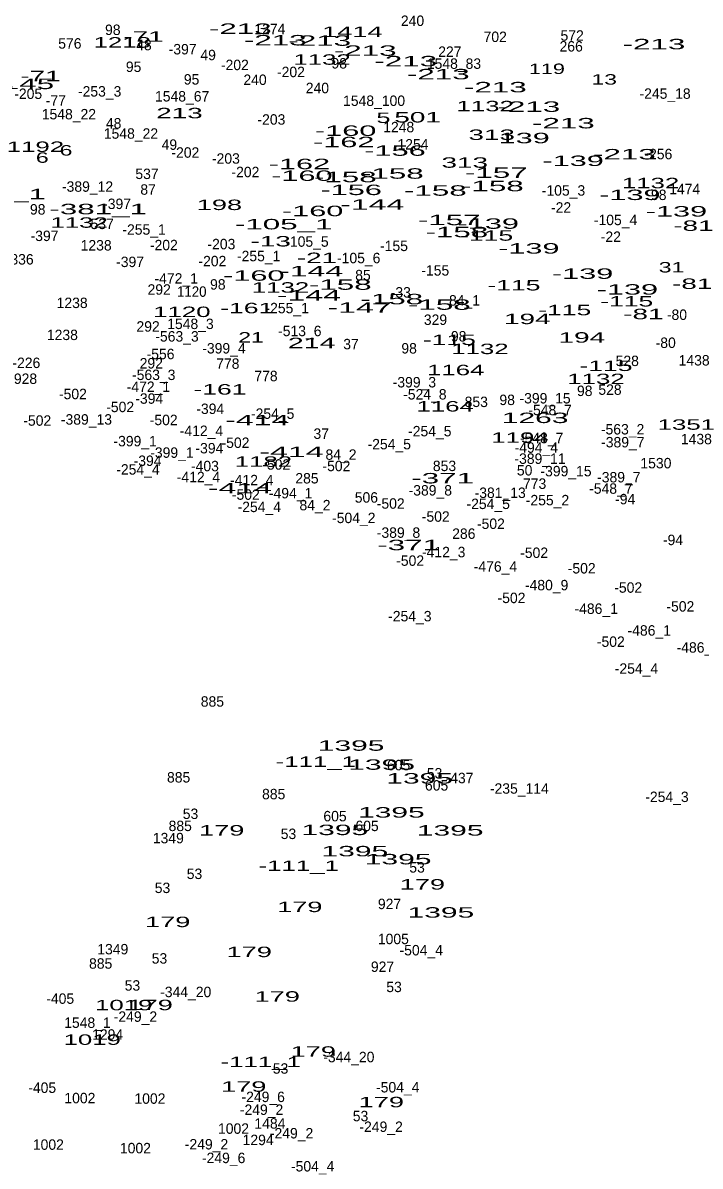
# Model space of a CAD drawing. Extents: x -660434 to -656144, y -997850 to -994016.
# Drawn here: x -659029.2 to -658769.3, y -995192.7 to -994753.9 of the extents above; entities that cross this region are included whole.
import ezdxf
from ezdxf.enums import TextEntityAlignment as Align

# ---------------------------------------------------------------- set-up
doc = ezdxf.new("R2010")
doc.units = 0
doc.header["$LTSCALE"] = 1.6
doc.layers.add('24', color=7, linetype='Continuous')

msp = doc.modelspace()

# ---------------------------------------------------------------- texts
at = {"layer": '24'}
for s, p in [('240', (-658879.695, -994755.04)), ('98', (-658994.713, -994758.51)), ('1274', (-658934.46, -994758.2)), ('702', (-658847.967, -994761.2)), ('572', (-658818.443, -994760.7)), ('576', (-659011.198, -994763.75)), ('48', (-658982.771, -994764.35)), ('266', (-658818.808, -994764.86)), ('-397', (-658967.925, -994765.96)), ('49', (-658958.127, -994768.19)), ('227', (-658865.373, -994766.91)), ('95', (-658986.733, -994772.71)), ('-202', (-658947.869, -994772)), ('98', (-658907.813, -994771.38)), ('1548_83', (-658863.792, -994771.5)), ('95', (-658964.483, -994777.53)), ('240', (-658940.135, -994777.68)), ('-202', (-658926.359, -994774.69)), ('-205', (-659027.179, -994783.06)), ('-253_3', (-658999.762, -994782.14)), ('240', (-658916.205, -994780.86)), ('-245_18', (-658782.779, -994783)), ('-77', (-659016.565, -994785.64)), ('1548_67', (-658968.103, -994784.04)), ('1548_100', (-658894.454, -994785.74)), ('1548_22', (-659011.562, -994790.9)), ('48', (-658994.391, -994794.41)), ('-203', (-658933.849, -994792.93)), ('1248', (-658884.994, -994795.85)), ('1548_22', (-658987.752, -994798.32)), ('49', (-658973.007, -994802.58)), ('1254', (-658879.524, -994802.47)), ('-202', (-658966.869, -994805.61)), ('-203', (-658951.319, -994807.91)), ('-256', (-658785.36, -994806.2)), ('537', (-658981.603, -994813.8)), ('-202', (-658943.829, -994813.1)), ('-389_12', (-659004.411, -994818.68)), ('87', (-658981.173, -994819.82)), ('-105_3', (-658821.76, -994820.17)), ('98', (-658785.203, -994821.86)), ('1474', (-658775.244, -994819.63)), ('-397', (-658993.085, -994825.31)), ('-22', (-658822.695, -994826.7)), ('98', (-659023.533, -994827.43)), ('-105_4', (-658801.784, -994831.5)), ('537', (-658998.783, -994833.01)), ('-255_1', (-658982.716, -994835.17)), ('-397', (-659020.925, -994837.6)), ('-105_5', (-658920.21, -994839.79)), ('-22', (-658803.595, -994837.93)), ('1238', (-659001.1, -994841.23)), ('-202', (-658975.129, -994841.14)), ('-203', (-658953.049, -994840.76)), ('-155 ', (-658886.066, -994841.45)), ('336', (-659029.553, -994846.61)), ('-397', (-658988.085, -994847.59)), ('-202', (-658956.509, -994847.29)), ('-255_1', (-658938.746, -994845.35)), ('-105_6', (-658900.346, -994846.12)), ('85', (-658898.717, -994852.67)), ('-155 ', (-658870.226, -994850.86)), ('-472_1', (-658970.386, -994853.94)), ('98', (-658954.413, -994856.24)), ('292', (-658976.913, -994858.19)), ('-33', (-658884.195, -994859.29)), ('1238', (-659010.32, -994863.32)), ('-255_1', (-658927.806, -994865.32)), ('84_1', (-658859.743, -994862.36)), ('329', (-658870.893, -994869.79)), ('-80', (-658778.219, -994867.87)), ('292', (-658981.183, -994872.37)), ('1548_3', (-658964.913, -994871.38)), ('-513_6', (-658922.962, -994874.11)), ('1238', (-659014.06, -994875.61)), ('-563_3', (-658970.078, -994876.18)), ('37', (-658903.313, -994879.15)), ('98', (-658861.993, -994876.16)), ('-80', (-658782.539, -994878.63)), ('-556', (-658976.4, -994882.95)), ('-399_4', (-658952.058, -994880.76)), ('98', (-658881.003, -994880.77)), ('-226', (-659027.89, -994886.34)), ('292', (-658979.943, -994886.52)), ('778', (-658950.579, -994886.64)), ('528', (-658797.297, -994885.59)), ('1438', (-658771.624, -994885.37)), ('928', (-659028.223, -994892.44)), ('-563_3', (-658979.008, -994890.95)), ('778', (-658935.929, -994891.4)), ('-472_1', (-658981.046, -994895.52)), ('-399_3', (-658878.983, -994893.79)), ('98', (-658813.613, -994897.09)), ('528', (-658803.917, -994896.63)), ('-502', (-659010.029, -994898.3)), ('-394', (-658980.735, -994900.05)), ('-524_8', (-658874.957, -994898.42)), ('853', (-658855.237, -994901.32)), ('98', (-658843.373, -994900.55)), ('-399_15', (-658828.836, -994899.94)), ('-502', (-658991.889, -994903.27)), ('-394', (-658957.315, -994903.98)), ('-254_5', (-658933.367, -994905.85)), ('-548_7', (-658826.912, -994904.44)), ('-502', (-659023.709, -994908.49)), ('-389_13', (-659004.841, -994908.06)), ('-502', (-658975.189, -994908.27)), ('-412_4', (-658960.685, -994912.42)), ('37', (-658914.733, -994913.53)), ('-254_5', (-658873.077, -994912.57)), ('-563_2', (-658799.078, -994911.84)), ('-399_1', (-658986.147, -994916.39)), ('-394', (-658957.655, -994919.11)), ('-502', (-658947.639, -994917.01)), ('-254_5', (-658888.627, -994917.56)), ('-494_4', (-658832.21, -994918.88)), ('-548_7', (-658830.172, -994915.2)), ('-389_7', (-658798.994, -994916.8)), ('1438', (-658770.764, -994915.6)), ('-399_1', (-658972.027, -994920.8)), ('84_2', (-658907.14, -994921.56)), ('-389_11', (-658830.775, -994923.12)), ('-254_4', (-658985.061, -994927.25)), ('-394', (-658981.375, -994923.92)), ('-403', (-658959.363, -994925.96)), ('-502', (-658931.989, -994925.36)), ('-502', (-658908.909, -994925.94)), ('853', (-658867.427, -994925.9)), ('50', (-658836.671, -994927.58)), ('-399_15', (-658820.796, -994927.9)), ('1530', (-658786.294, -994924.85)), ('-412_4', (-658961.835, -994930.18)), ('-412_4', (-658941.385, -994931.34)), ('285', (-658920.207, -994930.65)), ('-389_7', (-658800.534, -994930.24)), ('-494_1', (-658926.5, -994936.37)), ('-389_8', (-658872.878, -994935.28)), ('-381_13', (-658846.059, -994936.21)), ('773', (-658832.839, -994932.72)), ('-548_7', (-658803.582, -994934.6)), ('-502', (-658943.669, -994936.91)), ('84_2', (-658917.13, -994940.96)), ('506', (-658897.397, -994938.01)), ('-502', (-658888.069, -994940.34)), ('-254_5', (-658850.657, -994940.47)), ('-255_2', (-658827.902, -994939.04)), ('-94', (-658798.085, -994938.65)), ('-254_4', (-658938.511, -994941.64)), ('-502', (-658870.789, -994945.34)), ('-504_2', (-658902.241, -994945.87)), ('-502', (-658849.629, -994948.1)), ('-389_8', (-658885.078, -994951.51)), ('286', (-658860.013, -994951.91)), ('-94', (-658779.745, -994954.31)), ('-502', (-658880.609, -994962.26)), ('-412_3', (-658867.73, -994958.97)), ('-502', (-658833.029, -994959.24)), ('-476_4', (-658847.882, -994964.53)), ('-502', (-658814.779, -994965.2)), ('-480_9', (-658828.236, -994971.66)), ('-502', (-658796.929, -994972.59)), ('-502', (-658841.719, -994976.57)), ('-486_1', (-658809.206, -994980.71)), ('-502', (-658776.919, -994979.83)), ('-254_3', (-658880.727, -994983.58)), ('-486_1', (-658788.856, -994989.06)), ('-502', (-658803.609, -994993.37)), ('-486_1', (-658770.036, -994995.59)), ('-254_4', (-658793.751, -995003.68)), ('885', (-658956.497, -995016.33)), ('605', (-658885.047, -995040.75)), ('885', (-658969.457, -995045.43)), ('53', (-658871.237, -995043.89)), ('-437', (-658861.665, -995045.7)), ('605', (-658870.457, -995048.53)), ('-235_114', (-658838.703, -995049.73)), ('885', (-658932.977, -995051.87)), ('-254_3', (-658782.047, -995052.92)), ('53', (-658964.897, -995059.43)), ('885', (-658968.837, -995064.08)), ('605', (-658909.437, -995060.34)), ('605', (-658897.147, -995064.09)), ('53', (-658927.307, -995067.13)), ('1349', (-658973.41, -995068.76)), ('53', (-658877.957, -995080)), ('53', (-658963.367, -995082.48)), ('53', (-658975.647, -995087.86)), ('927', (-658888.528, -995094.03)), ('1005', (-658887.058, -995107.48)), ('1349', (-658994.72, -995111.4)), ('-504_4', (-658876.355, -995111.79)), ('53', (-658976.807, -995114.94)), ('885', (-658999.367, -995116.9)), ('927', (-658891.218, -995118.14)), ('53', (-658987.177, -995125.32)), ('-344_20', (-658966.734, -995127.82)), ('53', (-658886.787, -995125.89)), ('-405', (-659014.903, -995130.38)), ('-249_2', (-658986.032, -995137.29)), ('1548_1', (-659004.447, -995139.62)), ('1294', (-658996.7, -995144.15)), ('-344_20', (-658904.134, -995152.79)), ('53', (-658930.337, -995157.2)), ('-405', (-659021.813, -995164.57)), ('-504_4', (-658885.375, -995164.4)), ('1002', (-659007.348, -995168.55)), ('1002', (-658980.468, -995168.74)), ('-249_6', (-658937.008, -995168.09)), ('-249_2', (-658937.642, -995173.02)), ('53', (-658899.657, -995175.45)), ('1002', (-658948.398, -995180.26)), ('1484', (-658934.419, -995178.29)), ('-249_2', (-658926.122, -995182.05)), ('-249_2', (-658891.752, -995179.55)), ('1002', (-659019.448, -995186.41)), ('-249_2', (-658958.762, -995186.27)), ('1294', (-658938.95, -995184.61)), ('1002', (-658986.038, -995187.76)), ('-249_6', (-658952.178, -995191.52)), ('-504_4', (-658918.015, -995194.73))]:
    msp.add_text(s, height=4, dxfattribs=at).set_placement(p, align=Align.CENTER)
for s, width, p in [('-71', 2, (-658982.935, -994761.08)), ('-213', 2.25, (-658945.801, -994758.08)), ('1414', 1.95, (-658902.785, -994759.27)), ('1218', 1.85, (-658991.104, -994763.33)), ('-213', 2.25, (-658932.361, -994762.5)), ('-213', 2.25, (-658915.321, -994762.66)), ('-213', 2.25, (-658787.061, -994764)), ('1132', 1.85, (-658914.404, -994769.92)), ('-213', 2.25, (-658897.851, -994766.5)), ('-213', 2.25, (-658882.301, -994770.53)), ('119', 1.55, (-658828.139, -994773.48)), ('-71', 2, (-659022.485, -994776.26)), ('-213', 2.25, (-658869.821, -994775.53)), ('13', 1.65, (-658806.137, -994777.55)), ('-145', 2.25, (-659029.266, -994779.27)), ('-213', 2.25, (-658847.931, -994780.52)), ('213', 2, (-658969.137, -994790.47)), ('1132', 1.85, (-658851.814, -994787.79)), ('-213', 2.25, (-658835.061, -994788.01)), ('5', 1.8, (-658890.871, -994792.28)), ('501', 2, (-658877.744, -994792.08)), ('-213', 2.25, (-658821.821, -994794.35)), ('-160', 2.2, (-658905.361, -994797.24)), ('313', 2, (-658849.327, -994798.79)), ('-139', 2.2, (-658838.815, -994800.05)), ('1192', 1.85, (-659024.409, -994803.39)), ('6', 1.65, (-659012.666, -994804.78)), ('-162', 2.2, (-658906.105, -994801.57)), ('-156', 2.2, (-658886.435, -994804.88)), ('6', 1.65, (-659021.786, -994807.56)), ('313', 2, (-658859.647, -994809.46)), ('-139', 2.2, (-658818.075, -994808.79)), ('-213', 2.25, (-658798.391, -994806.26)), ('-162', 2.2, (-658923.105, -994810.02)), ('-158', 2.25, (-658887.461, -994813.67)), ('-157', 2.25, (-658847.555, -994813.35)), ('-160', 2.2, (-658922.161, -994814.51)), ('-158', 2.25, (-658905.511, -994815.01)), ('1132', 1.85, (-658788.354, -994817.33)), ('-381_1', 2.25, (-659039.117, -994821.55)), ('-156', 2.2, (-658903.235, -994819.95)), ('-158', 2.25, (-658870.951, -994820.2)), ('-158', 2.25, (-658849.061, -994818.47)), ('-139', 2.2, (-658796.285, -994821.86)), ('198', 1.95, (-658953.803, -994825.7)), ('-144', 2.3, (-658895.172, -994825.58)), ('-381_1', 2.25, (-659000.327, -994827.31)), ('-160', 2.2, (-658918.031, -994828.05)), ('-139', 2.2, (-658778.425, -994828.19)), ('1132', 1.85, (-659007.644, -994832.49)), ('-105_1', 2.25, (-658929.144, -994833.12)), ('-157', 2.25, (-658865.605, -994831.5)), ('-139', 2.2, (-658850.625, -994832.9)), ('-81', 2, (-658771.901, -994833.7)), ('-13', 2, (-658934.131, -994839.67)), ('-158', 2.25, (-658862.691, -994836.14)), ('-115', 1.9, (-658851.247, -994837.47)), ('-139', 2.2, (-658835.065, -994842.41)), ('-21', 2, (-658916.371, -994846.04)), ('-160', 2.2, (-658940.601, -994852.83)), ('-144', 2.3, (-658918.602, -994851.13)), ('-139', 2.2, (-658814.425, -994852.11)), ('31', 1.65, (-658780.297, -994849.66)), ('1132', 1.85, (-658930.364, -994857.4)), ('-158', 2.25, (-658907.431, -994856.31)), ('-115', 1.9, (-658840.787, -994856.57)), ('-81', 2, (-658772.381, -994855.98)), ('1120', 0.95, (-658964.41, -994858.99)), ('-144', 2.3, (-658919.462, -994860.44)), ('-158', 2.25, (-658887.661, -994861.88)), ('-139', 2.2, (-658797.245, -994858.16)), ('-161', 1.9, (-658943.321, -994865.32)), ('-147', 2.3, (-658900.021, -994865.12)), ('-158', 2.25, (-658869.421, -994863.99)), ('-115', 1.9, (-658821.297, -994866.08)), ('-115', 1.9, (-658797.487, -994862.72)), ('1120', 1.85, (-658968.22, -994866.77)), ('194', 2, (-658835.658, -994869.49)), ('-81', 2, (-658791.101, -994867.6)), ('21', 1.65, (-658941.667, -994876.56)), ('214', 2.05, (-658918.423, -994878.72)), ('-115', 1.9, (-658865.547, -994877.51)), ('194', 2, (-658814.728, -994876.6)), ('1132', 1.85, (-658853.824, -994880.99)), ('-115', 1.9, (-658805.457, -994887.49)), ('1164', 1.85, (-658863.125, -994889.1)), ('1132', 1.85, (-658809.284, -994892.51)), ('-161', 1.9, (-658953.591, -994896.53)), ('1164', 1.85, (-658867.165, -994903.03)), ('-414', 2.3, (-658939.312, -994908.32)), ('1263', 2.15, (-658832.653, -994907.46)), ('1351', 1.85, (-658774.624, -994910.03)), ('1194', 1.85, (-658838.455, -994915.03)), ('-414', 2.3, (-658926.152, -994920.52)), ('1182', 1.85, (-658936.914, -994924.25)), ('-371', 2.25, (-658868.135, -994930.62)), ('-414', 2.3, (-658945.932, -994934.45)), ('-371', 2.25, (-658881.195, -994956.26)), ('1395', 2.15, (-658903.273, -995033.24)), ('-111_1', 1.85, (-658916.83, -995039.42)), ('1395', 2.15, (-658891.563, -995040.54)), ('1395', 2.15, (-658876.973, -995045.83)), ('1395', 2.15, (-658887.823, -995058.89)), ('179', 1.95, (-658952.927, -995065.78)), ('1395', 2.15, (-658909.513, -995065.61)), ('1395', 2.15, (-658865.253, -995065.8)), ('1395', 2.15, (-658901.833, -995073.77)), ('1395', 2.15, (-658885.223, -995076.85)), ('-111_1', 1.85, (-658923.36, -995079.37)), ('179', 1.95, (-658875.927, -995086.52)), ('179', 1.95, (-658922.967, -995095.17)), ('1395', 2.15, (-658868.813, -995097.29)), ('179', 1.95, (-658973.657, -995100.93)), ('179', 1.95, (-658942.367, -995112.45)), ('179', 1.95, (-658931.607, -995129.55)), ('1019', 1.85, (-658990.525, -995132.86)), ('179', 1.95, (-658980.377, -995132.81)), ('1019', 1.85, (-659002.615, -995146.12)), ('179', 1.95, (-658917.787, -995150.68)), ('-111_1', 1.85, (-658937.95, -995154.67)), ('179', 1.95, (-658944.477, -995164.12)), ('179', 1.95, (-658891.677, -995170.08))]:
    msp.add_text(s, height=4, dxfattribs=dict(at, width=width)).set_placement(p, align=Align.CENTER)

doc.saveas('drawing.dxf')
